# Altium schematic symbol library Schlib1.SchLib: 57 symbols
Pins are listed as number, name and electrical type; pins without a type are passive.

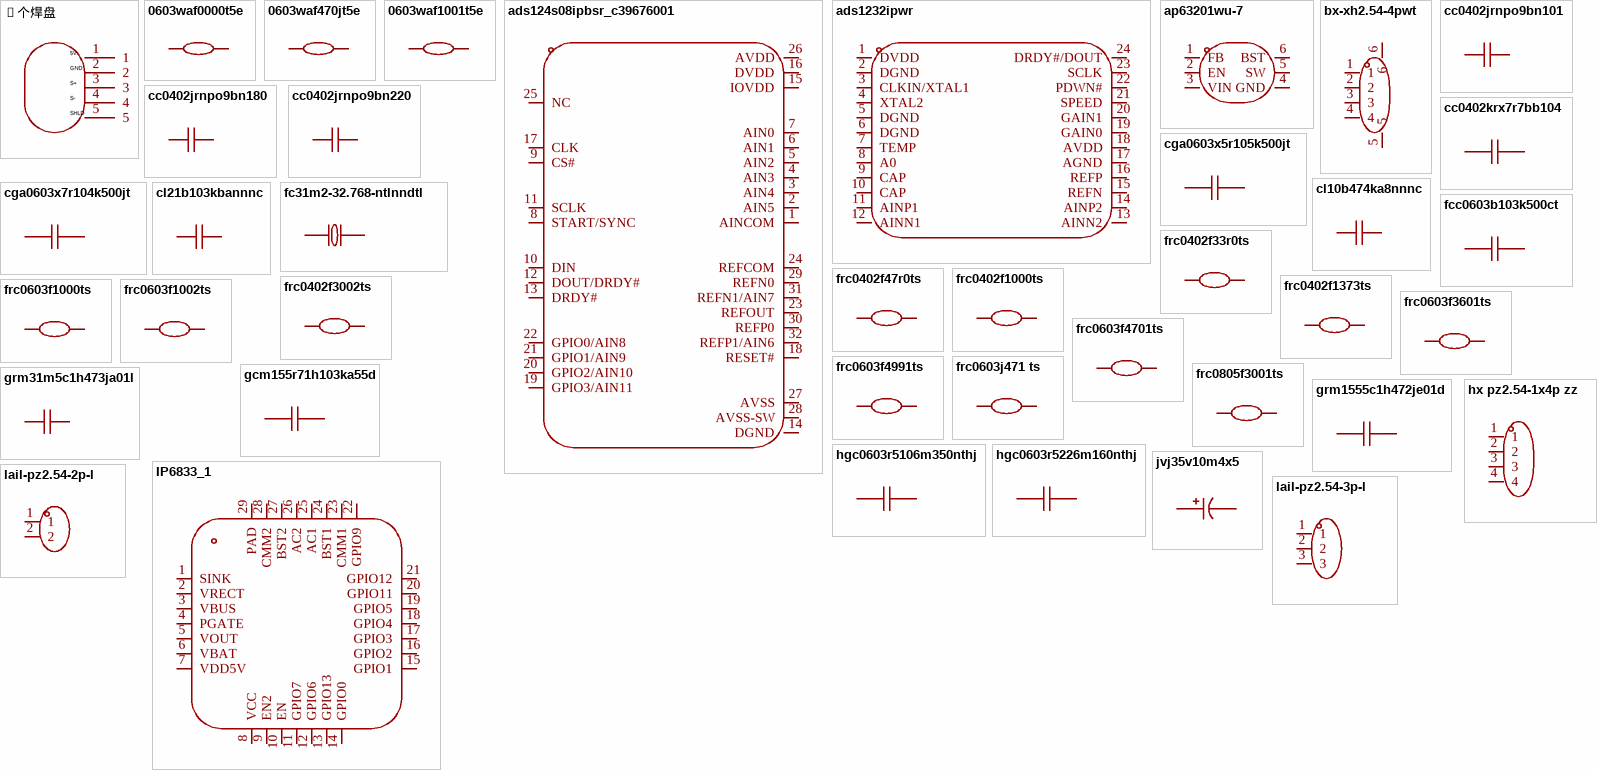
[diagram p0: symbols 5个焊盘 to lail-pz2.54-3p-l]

## 5个焊盘
designator U??  (value not drawn)
Convert to PCB: yes
pins: 1, 2, 3, 4, 5

## 0603waf0000t5e
designator R??  (value not drawn)
电阻类型:厚膜电阻;阻值:0Ω;精度:±1%;功率:100mW;工作电压:75V;温度系数:-;; Manufacturer: UNI-ROYAL(厚声); AddInBom: yes; ModelId: fc143cca1e79419f9cd78b61e9279f08; ModelName: R0603; ModelTransform: 31.8897,63.7794,0,90,0,0,0,0,0; Value: 0Ω; Tolerance: ±1%; Power(Watts): 100mW; Voltage-Supply(Max): 75V
footprint R0603
pins: 1, 2

## 0603waf470jt5e
designator R??  (value not drawn)
电阻类型:厚膜电阻;阻值:47Ω;精度:±1%;功率:100mW;工作电压:75V;温度系数:±100ppm/℃;; Manufacturer: UNI-ROYAL(厚声); AddInBom: yes; ModelId: fc143cca1e79419f9cd78b61e9279f08; ModelName: R0603; ModelTransform: 31.8897,63.7794,0,90,0,0,0,0,0; Value: 47Ω; Tolerance: ±1%; Power(Watts): 100mW; Voltage-Supply(Max): 75V
footprint R0603
pins: 1, 2

## 0603waf1001t5e
designator R??  (value not drawn)
电阻类型:厚膜电阻;阻值:1kΩ;精度:±1%;功率:100mW;工作电压:75V;温度系数:±100ppm/℃;; Manufacturer: UNI-ROYAL(厚声); AddInBom: yes; ModelId: fc143cca1e79419f9cd78b61e9279f08; ModelName: R0603; ModelTransform: 31.8897,63.7794,0,90,0,0,0,0,0; Value: 1kΩ; Tolerance: ±1%; Power(Watts): 100mW; Voltage-Supply(Max): 75V
footprint R0603
pins: 1, 2

## ads124s08ipbsr_c39676001
designator U??  (value not drawn)
分辨率(位):24;采样率:4kHz;工作电压:2.7V~5.25V;接口类型:SPI;; Manufacturer: TI(德州仪器); AddInBom: yes; ModelId: 0723864a05e7424ab80b3c78d6a7d93a; ModelName: TQFP-32_L5.0-W5.0-H1.2-LS7.0-P0.50; ModelTransform: 277.58783,277.58783,0,90,0,0,0.013,0,0; Resolution (Bits): 24; Sampling Rate: 4kHz; number of channels: 12; Interface: SPI; differential input: 是; Clock/Oscillator: 内置; Clock Frequency: 4.096MHz; Programmable Gain: 支持; Quiescent Current (Iq): 280uA
footprint TQFP-32_L5.0-W5.0-P0.50-LS7.0-BL
pins: 1 AINCOM, 2 AIN5, 3 AIN4, 4 AIN3, 5 AIN2, 6 AIN1, 7 AIN0, 8 START/SYNC, 9 CS#, 10 DIN, 11 SCLK, 12 DOUT/DRDY#, 13 DRDY#, 14 DGND, 15 IOVDD, 16 DVDD, 17 CLK, 18 RESET#, 19 GPIO3/AIN11, 20 GPIO2/AIN10, 21 GPIO1/AIN9, 22 GPIO0/AIN8, 23 REFOUT, 24 REFCOM, 25 NC, 26 AVDD, 27 AVSS, 28 AVSS-SW, 29 REFN0, 30 REFP0, 31 REFN1/AIN7, 32 REFP1/AIN6

## ads1232ipwr
designator U??  (value not drawn)
分辨率(位):24;采样率:10Hz;工作电压:2.7V~5.3V;接口类型:SPI;; Manufacturer: TI(德州仪器); AddInBom: yes; ModelId: 57e278220af748a2882c4abba4094eb9; ModelName: TSSOP-24_L7.8-W4.4-H1.0-LS6.4-P0.65; ModelTransform: 252.188,307.086,0,90,0,0,0,0,0; Resolution (Bits): 24; Sampling Rate: 10Hz; number of channels: 2; Interface: SPI; differential input: 是; Clock/Oscillator: 内置；外置; Clock Frequency: 4.9152MHz；200kHz~8MHz; Voltage Reference: 外置; Programmable Gain: 支持; Temperature Sensors: 内置; ADC architecture: Sigma-Delta; Data rate: 80Hz；10Hz; Quiescent Current (Iq): 1.3uA; Full-Scale Range(FSR): 39mV；1.25V；19.5mV；2.5V
footprint TSSOP-24_L7.8-W4.4-P0.65-LS6.4-BL
footprint Model Name (Footprint not found)
pins: 1 DVDD, 2 DGND, 3 CLKIN/XTAL1, 4 XTAL2, 5 DGND, 6 DGND, 7 TEMP, 8 A0, 9 CAP, 10 CAP, 11 AINP1, 12 AINN1, 13 AINN2, 14 AINP2, 15 REFN, 16 REFP, 17 AGND, 18 AVDD, 19 GAIN0, 20 GAIN1, 21 SPEED, 22 PDWN#, 23 SCLK, 24 DRDY#/DOUT

## ap63201wu-7
designator U??  (value not drawn)
功能类型:降压型;工作电压:3.8V~32V;输出电压:-;输出电流:2A;输出类型:可调;; Manufacturer: DIODES(美台); AddInBom: yes; ModelId: 2c4039b5b88644c1bda4b4ba9e971667; ModelName: TSOT-23-6_L2.9-W1.6-H1.1-LS2.8-P0.95; ModelTransform: 110.45568,114.173,0,180,0,0,-0.005,-0.0005,0; Function: 降压型; Output Current: 2A; Frequency - Switching: 500kHz; Synchronous Rectifier: 是; Number of Outputs: 1; Topology: 降压式; Quiescent Current: 22uA; Switch tube (built-in/external): 内置; Output Type: 可调
footprint TSOT-23-6_L2.9-W1.6-P0.95-LS2.8-BR
pins: 1 FB, 2 EN, 3 VIN, 4 GND, 5 SW, 6 BST

## bx-xh2.54-4pwt
designator U??  (value not drawn)
插针结构:1x4P;间距:2.5mm;安装方式:卧贴;参考系列:XH;总PIN数:4P;排数:1;每排PIN数:4;行距:-;额定电流:3A;触头材质:黄铜;触头镀层:锡;工作温度:-25℃~+85℃;; Manufacturer: Bossie(博锡); AddInBom: yes; ModelId: fc4292fdbd0c45d68488b12ac9a84ffb; ModelName: CONN-SMD_4P-P2.50_BX-XH2.54-4PWT; ModelTransform: 590.55,413.385,0,0,0,0,-0.003,-11.339,0; Pins Structure: 1x4P; Pitch: 2.5mm; Reference Series: XH; Number of PINs Per Row: 4; Current Rating: 3A; Voltage Rating: 250V; Supplementary Features: 辅助焊脚; Z-Height of the Board: 6.2mm; X-Length of Bottom Edge on Board (Spacing Line): 15mm; Y-Width of Bottom Edge on Board: 10.5mm
footprint CONN-SMD_4P-P2.50_BX-XH2.54-4PWT
pins: 1, 2, 3, 4, 5, 6

## cc0402jrnpo9bn101
designator C??  (value not drawn)
容值:100pF;精度:±5%;额定电压:50V;温度系数:NP0;; Manufacturer: YAGEO(国巨); AddInBom: yes; ModelId: 36a51122f27c49738f86b3bfa98863e0; ModelName: C0402_L1.0-W0.5-H0.5; ModelTransform: 39.37,19.685,0,0,0,0,0,0,0; Value: 100pF; Tolerance: ±5%; Voltage Rating: 50V; Temperature Coefficient: NP0
footprint C0402
pins: 1, 2

## cc0402jrnpo9bn180
designator C??  (value not drawn)
容值:18pF;精度:±5%;额定电压:50V;温度系数:NP0;; Manufacturer: YAGEO(国巨); AddInBom: yes; ModelId: 36a51122f27c49738f86b3bfa98863e0; ModelName: C0402_L1.0-W0.5-H0.5; ModelTransform: 39.37,19.685,0,0,0,0,0,0,0; Value: 18pF; Tolerance: ±5%; Voltage Rating: 50V; Temperature Coefficient: NP0
footprint C0402
pins: 1, 2

## cc0402jrnpo9bn220
designator C??  (value not drawn)
容值:22pF;精度:±5%;额定电压:50V;温度系数:NP0;; Manufacturer: YAGEO(国巨); AddInBom: yes; ModelId: 36a51122f27c49738f86b3bfa98863e0; ModelName: C0402_L1.0-W0.5-H0.5; ModelTransform: 39.37,19.685,0,0,0,0,0,0,0; Value: 22pF; Tolerance: ±5%; Voltage Rating: 50V; Temperature Coefficient: NP0
footprint C0402
pins: 1, 2

## cc0402krx7r7bb104
designator C??  (value not drawn)
容值:100nF;精度:±10%;额定电压:16V;温度系数:X7R;; Manufacturer: YAGEO(国巨); AddInBom: yes; ModelId: 36a51122f27c49738f86b3bfa98863e0; ModelName: C0402_L1.0-W0.5-H0.5; ModelTransform: 39.37,19.685,0,0,0,0,0,0,0; Value: 100nF; Tolerance: ±10%; Voltage Rating: 16V; Temperature Coefficient: X7R
footprint C0402
pins: 1, 2

## cga0603x5r105k500jt
designator C??  (value not drawn)
容值:1uF;精度:±10%;额定电压:50V;温度系数:X5R;; Manufacturer: HRE(芯声); AddInBom: yes; ModelId: ac125912035d415993ca9572d50418b1; ModelName: C0603_L1.6-W0.8-H0.8; ModelTransform: 62.992,31.496,0,0,0,0,0,0,0; Value: 1uF; Tolerance: ±10%; Voltage Rating: 50V; Temperature Coefficient: X5R
footprint C0603
pins: 1, 2

## cga0603x7r104k500jt
designator C??  (value not drawn)
容值:100nF;精度:±10%;额定电压:50V;温度系数:X7R;; Manufacturer: HRE(芯声); AddInBom: yes; ModelId: ac125912035d415993ca9572d50418b1; ModelName: C0603_L1.6-W0.8-H0.8; ModelTransform: 62.992,31.496,0,0,0,0,0,0,0; Value: 100nF; Tolerance: ±10%; Voltage Rating: 50V; Temperature Coefficient: X7R
footprint C0603
footprint Model Name (Footprint not found)
pins: 1, 2

## cl10b474ka8nnnc
designator C??  (value not drawn)
容值:470nF;精度:±10%;额定电压:25V;温度系数:X7R;; Manufacturer: SAMSUNG(三星); AddInBom: yes; ModelId: ac125912035d415993ca9572d50418b1; ModelName: C0603_L1.6-W0.8-H0.8; ModelTransform: 62.992,31.496,0,0,0,0,0,0,0; Value: 470nF; Tolerance: ±10%; Voltage Rating: 25V; Temperature Coefficient: X7R
footprint C0603
pins: 1, 2

## cl21b103kbannnc
designator C??  (value not drawn)
容值:10nF;精度:±10%;额定电压:50V;温度系数:X7R;; Manufacturer: SAMSUNG(三星); AddInBom: yes; ModelId: 1ba041120af144c991958decab20d241; ModelName: C0805_L2.0-W1.3-H1.3; ModelTransform: 78.74,51.181,0,0,0,0,0,0.0005,0; Value: 10nF; Tolerance: ±10%; Voltage Rating: 50V; Temperature Coefficient: X7R
footprint C0805
pins: 1, 2

## fc31m2-32.768-ntlnndtl
designator U??  (value not drawn)
晶振类型:贴片晶振;频率:32.768kHz;常温频差:±10ppm;负载电容:12.5pF;频率稳定度:±10ppm;; Manufacturer: HCI(杭晶); AddInBom: yes; ModelId: 762d7afc596f4558a373612390f4386d; ModelName: CRYSTAL-SMD_L3.2-W1.5-1; ModelTransform: 125.984,59.055,0,0,0,0,0,0,0; Normal temperature Frequency Tolerance: ±10ppm; Load Capacitance: 12.5pF; Equivalent Series Resistance(ESR): 70kΩ
footprint CRYSTAL-SMD_L3.2-W1.5
pins: 1, 2

## fcc0603b103k500ct
designator C??  (value not drawn)
容值:10nF;精度:±10%;额定电压:50V;温度系数:X7R;; Manufacturer: FOJAN(富捷); AddInBom: yes; ModelId: ac125912035d415993ca9572d50418b1; ModelName: C0603_L1.6-W0.8-H0.8; ModelTransform: 62.992,31.496,0,0,0,0,0,0,0; Value: 10nF; Tolerance: ±10%; Voltage Rating: 50V; Temperature Coefficient: X7R
footprint C0603
pins: 1, 2

## frc0402f33r0ts
designator R??  (value not drawn)
电阻类型:厚膜电阻;阻值:33Ω;精度:±1%;功率:62.5mW;工作电压:50V;温度系数:±100ppm/℃;; Manufacturer: FOJAN(富捷); AddInBom: yes; ModelId: 98c88bc2b9094f218f3a3e30a7012738; ModelName: R0402_L1.0-W0.5-H0.4; ModelTransform: 39.37,19.685,0,0,0,0,0,0,0; Value: 33Ω; Tolerance: ±1%; Power(Watts): 62.5mW; Voltage-Supply(Max): 50V
footprint R0402
pins: 1, 2

## frc0402f47r0ts
designator R??  (value not drawn)
电阻类型:厚膜电阻;阻值:47Ω;精度:±1%;功率:62.5mW;工作电压:50V;温度系数:±100ppm/℃;; Manufacturer: FOJAN(富捷); AddInBom: yes; ModelId: 98c88bc2b9094f218f3a3e30a7012738; ModelName: R0402_L1.0-W0.5-H0.4; ModelTransform: 39.37,19.685,0,0,0,0,0,0,0; Value: 47Ω; Tolerance: ±1%; Power(Watts): 62.5mW; Voltage-Supply(Max): 50V
footprint R0402
pins: 1, 2

## frc0402f1000ts
designator R??  (value not drawn)
电阻类型:厚膜电阻;阻值:100Ω;精度:±1%;功率:62.5mW;工作电压:50V;温度系数:±100ppm/℃;; Manufacturer: FOJAN(富捷); AddInBom: yes; ModelId: 98c88bc2b9094f218f3a3e30a7012738; ModelName: R0402_L1.0-W0.5-H0.4; ModelTransform: 39.37,19.685,0,0,0,0,0,0,0; Value: 100Ω; Tolerance: ±1%; Power(Watts): 62.5mW; Voltage-Supply(Max): 50V
footprint R0402
pins: 1, 2

## frc0402f1373ts
designator R??  (value not drawn)
电阻类型:厚膜电阻;阻值:137kΩ;精度:±1%;功率:62.5mW;工作电压:50V;温度系数:±100ppm/℃;; Manufacturer: FOJAN(富捷); AddInBom: yes; ModelId: 98c88bc2b9094f218f3a3e30a7012738; ModelName: R0402_L1.0-W0.5-H0.4; ModelTransform: 39.37,19.685,0,0,0,0,0,0,0; Value: 137kΩ; Tolerance: ±1%; Power(Watts): 62.5mW; Voltage-Supply(Max): 50V
footprint R0402
pins: 1, 2

## frc0402f3002ts
designator R??  (value not drawn)
电阻类型:厚膜电阻;阻值:30kΩ;精度:±1%;功率:62.5mW;工作电压:50V;温度系数:±100ppm/℃;; Manufacturer: FOJAN(富捷); AddInBom: yes; ModelId: 98c88bc2b9094f218f3a3e30a7012738; ModelName: R0402_L1.0-W0.5-H0.4; ModelTransform: 39.37,19.685,0,0,0,0,0,0,0; Value: 30kΩ; Tolerance: ±1%; Power(Watts): 62.5mW; Voltage-Supply(Max): 50V
footprint R0402
pins: 1, 2

## frc0603f1000ts
designator R??  (value not drawn)
电阻类型:厚膜电阻;阻值:100Ω;精度:±1%;功率:100mW;工作电压:75V;温度系数:±100ppm/℃;; Manufacturer: FOJAN(富捷); AddInBom: yes; ModelId: fc143cca1e79419f9cd78b61e9279f08; ModelName: R0603; ModelTransform: 31.8897,63.7794,0,90,0,0,0,0,0; Value: 100Ω; Tolerance: ±1%; Power(Watts): 100mW; Voltage-Supply(Max): 75V
footprint R0603
pins: 1, 2

## frc0603f1002ts
designator R??  (value not drawn)
电阻类型:厚膜电阻;阻值:10kΩ;精度:±1%;功率:100mW;工作电压:75V;温度系数:±100ppm/℃;; Manufacturer: FOJAN(富捷); AddInBom: yes; ModelId: fc143cca1e79419f9cd78b61e9279f08; ModelName: R0603; ModelTransform: 31.8897,63.7794,0,90,0,0,0,0,0; Value: 10kΩ; Tolerance: ±1%; Power(Watts): 100mW; Voltage-Supply(Max): 75V
footprint R0603
pins: 1, 2

## frc0603f3601ts
designator R??  (value not drawn)
电阻类型:厚膜电阻;阻值:3.6kΩ;精度:±1%;功率:100mW;工作电压:75V;温度系数:±100ppm/℃;; Manufacturer: FOJAN(富捷); AddInBom: yes; ModelId: fc143cca1e79419f9cd78b61e9279f08; ModelName: R0603; ModelTransform: 31.8897,63.7794,0,90,0,0,0,0,0; Value: 3.6kΩ; Tolerance: ±1%; Power(Watts): 100mW; Voltage-Supply(Max): 75V
footprint R0603
pins: 1, 2

## frc0603f4701ts
designator R??  (value not drawn)
电阻类型:厚膜电阻;阻值:4.7kΩ;精度:±1%;功率:100mW;工作电压:75V;温度系数:±100ppm/℃;; Manufacturer: FOJAN(富捷); AddInBom: yes; ModelId: fc143cca1e79419f9cd78b61e9279f08; ModelName: R0603; ModelTransform: 31.8897,63.7794,0,90,0,0,0,0,0; Value: 4.7kΩ; Tolerance: ±1%; Power(Watts): 100mW; Voltage-Supply(Max): 75V
footprint R0603
pins: 1, 2

## frc0603f4991ts
designator R??  (value not drawn)
电阻类型:厚膜电阻;阻值:4.99kΩ;精度:±1%;功率:100mW;工作电压:75V;温度系数:±100ppm/℃;; Manufacturer: FOJAN(富捷); AddInBom: yes; ModelId: fc143cca1e79419f9cd78b61e9279f08; ModelName: R0603; ModelTransform: 31.8897,63.7794,0,90,0,0,0,0,0; Value: 4.99kΩ; Tolerance: ±1%; Power(Watts): 100mW; Voltage-Supply(Max): 75V
footprint R0603
pins: 1, 2

## frc0603j471 ts
designator R??  (value not drawn)
电阻类型:厚膜电阻;阻值:470Ω;精度:±5%;功率:100mW;工作电压:75V;温度系数:±100ppm/℃;; Manufacturer: FOJAN(富捷); AddInBom: yes; ModelId: fc143cca1e79419f9cd78b61e9279f08; ModelName: R0603; ModelTransform: 31.8897,63.7794,0,90,0,0,0,0,0; Value: 470Ω; Tolerance: ±5%; Power(Watts): 100mW; Voltage-Supply(Max): 75V
footprint R0603
pins: 1, 2

## frc0805f3001ts
designator R??  (value not drawn)
电阻类型:厚膜电阻;阻值:3kΩ;精度:±1%;功率:125mW;工作电压:150V;温度系数:±100ppm/℃;; Manufacturer: FOJAN(富捷); AddInBom: yes; ModelId: 37a81e68749a4138bd2dfa6897b24b85; ModelName: R0805_L2.0-W1.3-H0.6; ModelTransform: 78.74,51.181,0,0,0,0,0,-0.0005,0; Value: 3kΩ; Tolerance: ±1%; Power(Watts): 125mW; Voltage-Supply(Max): 150V
footprint R0805
pins: 1, 2

## gcm155r71h103ka55d
designator C??  (value not drawn)
容值:10nF;精度:±10%;额定电压:50V;温度系数:X7R;; Manufacturer: muRata(村田); AddInBom: yes; ModelId: 36a51122f27c49738f86b3bfa98863e0; ModelName: C0402_L1.0-W0.5-H0.5; ModelTransform: 39.37,19.685,0,0,0,0,0,0,0; Value: 10nF; Tolerance: ±10%; Voltage Rating: 50V; Temperature Coefficient: X7R
footprint C0402
pins: 1, 2

## grm31m5c1h473ja01l
designator C??  (value not drawn)
容值:47nF;精度:±5%;额定电压:50V;温度系数:C0G;; Manufacturer: muRata(村田); AddInBom: yes; ModelId: e4be705b945545a48e666415e3682bd8; ModelName: C1206_L3.2-W1.6-H1.3; ModelTransform: 125.984,62.992,0,0,0,0,0,0,0; Value: 47nF; Tolerance: ±5%; Voltage Rating: 50V; Temperature Coefficient: C0G
footprint C1206
pins: 1, 2

## grm1555c1h472je01d
designator C??  (value not drawn)
容值:4.7nF;精度:±5%;额定电压:50V;温度系数:C0G;; Manufacturer: muRata(村田); AddInBom: yes; ModelId: 36a51122f27c49738f86b3bfa98863e0; ModelName: C0402_L1.0-W0.5-H0.5; ModelTransform: 39.37,19.685,0,0,0,0,0,0,0; Value: 4.7nF; Tolerance: ±5%; Voltage Rating: 50V; Temperature Coefficient: C0G
footprint C0402
pins: 1, 2

## hgc0603r5106m350nthj
designator C??  (value not drawn)
容值:10uF;精度:±20%;额定电压:35V;温度系数:X5R;; Manufacturer: Chinocera(华瓷); AddInBom: yes; ModelId: ac125912035d415993ca9572d50418b1; ModelName: C0603_L1.6-W0.8-H0.8; ModelTransform: 62.992,31.496,0,0,0,0,0,0,0; Value: 10uF; Tolerance: ±20%; Voltage Rating: 35V; Temperature Coefficient: X5R
footprint C0603
pins: 1, 2

## hgc0603r5226m160nthj
designator C??  (value not drawn)
容值:22uF;精度:±20%;额定电压:16V;温度系数:X5R;; Manufacturer: Chinocera(华瓷); AddInBom: yes; ModelId: ac125912035d415993ca9572d50418b1; ModelName: C0603_L1.6-W0.8-H0.8; ModelTransform: 62.992,31.496,0,0,0,0,0,0,0; Value: 22uF; Tolerance: ±20%; Voltage Rating: 16V; Temperature Coefficient: X5R
footprint C0603
pins: 1, 2

## hx pz2.54-1x4p zz
designator U??  (value not drawn)
插针结构:1x4P;间距:2.54mm;行距:-;圆针/方针:方针;安装方式:直插;排数:单排;总PIN位数:4P;额定电流:3A;额定电压:1kV;配合针长度:6mm;塑高:2.5mm;端接针长度:3mm;触头材质:黄铜;触头镀层:金;工作温度:-40℃~+105℃;颜色:黑色;; Manufacturer: hanxia(韩下); AddInBom: yes; ModelId: 112f4d05e8d64e99ab9a333894bea4f9; ModelName: HDR-TH_4P-P2.54-M-LI-1X4P; ModelTransform: 399.999,104.7242,0,0,0,0,0,0,-118.11; Pin Structure: 1x4P; Pitch: 2.54mm; Circluar Pins/Square Pins: 方针; Current Rating: 3A; Voltage Rating (Max): 1kV
footprint HDR-TH_4P-P2.54-V-M
pins: 1, 2, 3, 4

## IP6833_1
designator U??  (value not drawn)
pins: 1 SINK, 2 VRECT, 3 VBUS, 4 PGATE, 5 VOUT, 6 VBAT, 7 VDD5V, 8 VCC, 9 EN2, 10 EN, 11 GPIO7, 12 GPIO6, 13 GPIO13, 14 GPIO0, 15 GPIO1, 16 GPIO2, 17 GPIO3, 18 GPIO4, 19 GPIO5, 20 GPIO11, 21 GPIO12, 22 GPIO9, 23 CMM1, 24 BST1, 25 AC1, 26 AC2, 27 BST2, 28 CMM2, 29 PAD

## jvj35v10m4x5
designator C??  (value not drawn)
容值:10uF;精度:±20%;额定电压:35V;纹波电流:14mA@120Hz;; Manufacturer: JIERR(捷而瑞); AddInBom: yes; ModelId: d5abac2407cc4bb7a22453350802a0e2; ModelName: CAP-SMD_L4.3-W4.3-H5.3-LS5.1; ModelTransform: 169.291,181.102,0,90,0,0,0.376,-0.001,0; Value: 10uF; Tolerance: ±20%; Voltage Rating: 35V; Lifetime: 2000hrs@105℃
footprint CAP-SMD_BD4.0-L4.3-W4.3-FD
pins: 1, 2

## lail-pz2.54-2p-l
designator H??  (value not drawn)
插针结构:1x2P;间距:2.54mm;圆针/方针:方针;排数:单排;总PIN位数:2P;额定电流:3A;额定电压:250V;塑高:2.5mm;端接针长度:3mm;触头材质:黄铜;触头镀层:金;工作温度:-25℃~+80℃;颜色:黑色;; Manufacturer: 莱联; AddInBom: yes; Pin Structure: 1x2P; Pitch: 2.54mm; Circluar Pins/Square Pins: 方针; Current Rating: 3A; Voltage Rating (Max): 250V
footprint CONN-TH_LAIL-PZ2.54-2P-L
pins: 1, 2

## lail-pz2.54-3p-l
designator H??  (value not drawn)
插针结构:1x3P;间距:2.54mm;圆针/方针:方针;排数:单排;总PIN位数:3P;额定电流:3A;额定电压:250V;塑高:2.5mm;端接针长度:3mm;触头材质:黄铜;触头镀层:金;工作温度:-25℃~+80℃;颜色:黑色;; Manufacturer: LAILAN(莱联); AddInBom: yes; ModelId: 94a8ffe137b6410295cb18cd3ffd99db; ModelName: HDR-M-2.54_1x3; ModelTransform: 299.9994,100,0,0,0,0,0,0,-118.11; Pin Structure: 1x3P; Pitch: 2.54mm; Circluar Pins/Square Pins: 方针; Current Rating: 3A; Voltage Rating (Max): 250V
footprint HDR-TH_3P-P2.54-V-M-1
pins: 1, 2, 3

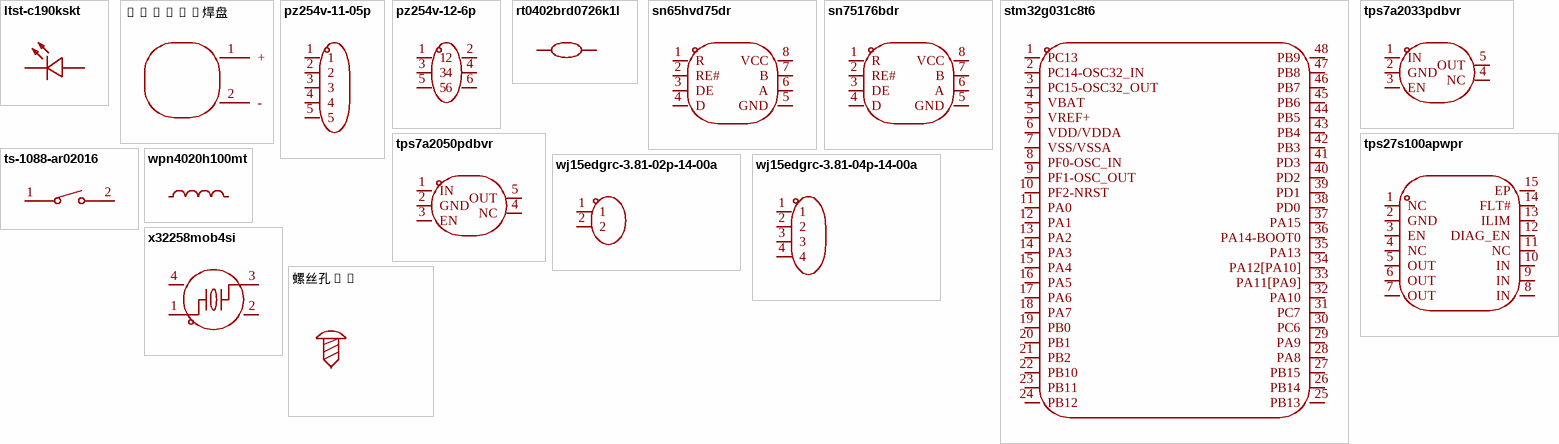
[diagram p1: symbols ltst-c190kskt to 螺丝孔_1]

## ltst-c190kskt
designator LED??  (value not drawn)
灯头类型:-;发光颜色:黄色;正向压降(Vf):2.1V;功率:75mW;正向电流:20mA;波长:584.5nm~597nm;二极管配置:独立二极管;透镜颜色:无色透明透镜;色温:-;发光强度:104mcd;发光角度:130°;载带方式:-;工作温度:-30℃~+85℃;; Manufacturer: LITEON(光宝); AddInBom: yes; ModelId: 1f0d29a91be547639d425604e9b96ebb; ModelName: LED0603-RD; ModelTransform: 63.7794,32.283,0,0,0,0,0,0,0; Illumination Color: 黄色; Voltage - Forward(Vf): 2.1V; Power(Watts): 75mW; Forward Current: 20mA; Peak Wavelength: 588nm; Diode Configuration: 独立二极管; Lens Color: 无色透明透镜; Luminous Intensity: 104mcd; Viewing Angle: 130°
footprint LED0603-RD
pins: 1 -, 2 +

## pt1000焊盘
designator U??  (value not drawn)
AddInBom: yes
footprint PT1000焊盘
pins: 1 +, 2 -

## pz254v-11-05p
designator H??  (value not drawn)
插针结构:1x5P;间距:2.54mm;行距:-;圆针/方针:方针;安装方式:直插;排数:单排;总PIN位数:5P;额定电流:3A;额定电压:250V;配合针长度:6mm;塑高:2.5mm;端接针长度:3mm;触头材质:黄铜;触头镀层:-;工作温度:-40℃~+105℃;颜色:黑色;; Manufacturer: XFCN(兴飞); AddInBom: yes; ModelId: 47d466e4a34f4fc5bc626cf773a24dd5; ModelName: HDR-TH_5P-P2.54-M-LI-1X5P; ModelTransform: 499.999,100,0,0,0,0,0,0,-118.11; Pin Structure: 1x5P; Pitch: 2.54mm; Circluar Pins/Square Pins: 方针; Current Rating: 3A; Voltage Rating (Max): 250V
footprint HDR-TH_5P-P2.54-V-M
pins: 1, 2, 3, 4, 5

## pz254v-12-6p
designator H??  (value not drawn)
插针结构:2x3P;间距:2.54mm;行距:2.54mm;圆针/方针:方针;安装方式:直插;排数:双排;总PIN位数:6P;额定电流:3A;额定电压:-;配合针长度:6mm;塑高:2.5mm;端接针长度:3mm;触头材质:黄铜;触头镀层:金;工作温度:-40℃~+105℃;颜色:黑色;; Manufacturer: XFCN(兴飞); AddInBom: yes; ModelId: e22692306cbd4b5c8488f4142eed6b9c; ModelName: HDR-TH_6P-P2.54-V-M-R2-C3-S2.54; ModelTransform: 300.3931,200,0,0,0,0,0,0,-118.11; Pin Structure: 2x3P; Pitch: 2.54mm; Circluar Pins/Square Pins: 方针; Current Rating: 3A
footprint HDR-TH_6P-P2.54-V-M-R2-C3-S2.54
pins: 1, 2, 3, 4, 5, 6

## rt0402brd0726k1l
designator R??  (value not drawn)
电阻类型:薄膜电阻;阻值:26.1kΩ;精度:±0.1%;功率:62.5mW;工作电压:50V;温度系数:±25ppm/℃;; Manufacturer: YAGEO(国巨); AddInBom: yes; ModelId: 98c88bc2b9094f218f3a3e30a7012738; ModelName: R0402_L1.0-W0.5-H0.4; ModelTransform: 39.37,19.685,0,0,0,0,0,0,0; Value: 26.1kΩ; Tolerance: ±0.1%; Power(Watts): 62.5mW; Voltage-Supply(Max): 50V
footprint R0402
pins: 1, 2

## sn65hvd75dr
designator U??  (value not drawn)
类型:收发器;数据速率:20Mbps;; Manufacturer: TI(德州仪器); AddInBom: yes; ModelId: e81d2f7d937b4a6ab1dca543ff5d56a4; ModelName: SOIC-8_L4.9-W3.9-H1.7-LS6.0-P1.27; ModelTransform: 192.913,236.22,0,0,0,0,0,0,0; Number of Drivers: 1; Voltage - Supply: 3V~3.6V; Data Rate: 20Mbps; Number of Nodes: 213; ESD Protect: ±15kV; Quiescent Supply Current: 950uA; Communication Mode: 半双工
footprint SOIC-8_L4.9-W3.9-P1.27-LS6.0-BL
pins: 1 R, 2 RE#, 3 DE, 4 D, 5 GND, 6 A, 7 B, 8 VCC

## sn75176bdr
designator U??  (value not drawn)
类型:收发器;数据速率:-;; Manufacturer: TI(德州仪器); AddInBom: yes; ModelId: 7abc64c95a1a4a04a4ef38f9097c870b; ModelName: SOIC-8_L5.0-W4.0-P1.27-LS6.0-BL; ModelTransform: 192.913,236.22,0,0,0,0,0,0,0; Number of Drivers: 1; Voltage - Supply: 4.75V~5.25V
footprint SOIC-8_L5.0-W4.0-P1.27-LS6.0-BL
pins: 1 R, 2 RE#, 3 DE, 4 D, 5 GND, 6 A, 7 B, 8 VCC

## stm32g031c8t6
designator U??  (value not drawn)
CPU内核:ARM Cortex-M0+;CPU最大主频:64MHz;CPU位数:32 Bit;; Manufacturer: ST(意法半导体); AddInBom: yes; ModelId: 093be70396ff421eb2cdb946d5311efc; ModelName: LQFP-48_L7.0-W7.0-H1.4-LS9.0-P0.50; ModelTransform: 354.331,354.331,0,0,0,0,0,0,0; CPU Maximum Speed: 64MHz; Core Size: 32 Bit; Program Storage Size: 64KB; Program Memory Type: FLASH; RAM Size: 8KB; Number of I/O: 44; ADC (Bit): 12bit; Oscillator Type: 内置+外置; Voltage - Supply: 1.7V~3.6V
footprint LQFP-48_L7.0-W7.0-P0.50-LS9.0-BL
pins: 1 PC13, 2 PC14-OSC32_IN, 3 PC15-OSC32_OUT, 4 VBAT, 5 VREF+, 6 VDD/VDDA, 7 VSS/VSSA, 8 PF0-OSC_IN, 9 PF1-OSC_OUT, 10 PF2-NRST, 11 PA0, 12 PA1, 13 PA2, 14 PA3, 15 PA4, 16 PA5, 17 PA6, 18 PA7, 19 PB0, 20 PB1, 21 PB2, 22 PB10, 23 PB11, 24 PB12, 25 PB13, 26 PB14, 27 PB15, 28 PA8, 29 PA9, 30 PC6, 31 PC7, 32 PA10, 33 PA11[PA9], 34 PA12[PA10], 35 PA13, 36 PA14-BOOT0, 37 PA15, 38 PD0, 39 PD1, 40 PD2, 41 PD3, 42 PB3, 43 PB4, 44 PB5, 45 PB6, 46 PB7, 47 PB8, 48 PB9

## tps7a2033pdbvr
designator U??  (value not drawn)
输出类型:固定;最大输入电压:6V;输出电压:3.3V;输出电流:300mA;输出极性:正极;; Manufacturer: TI(德州仪器); AddInBom: yes; ModelId: 7ba65df16e7b4570af156e925f9c37fe; ModelName: SOT-23-5_L2.9-W1.6-P0.95-LS2.8-BR; ModelTransform: 114.173,114.173,0,90,0,0,0,0,0; Output Type: 固定; Maximum Input Voltage: 6V; Output Voltage: 3.3V; Output Current: 300mA; Dropout Voltage: 140mV@(300mA); standby current: 15uA; Output Polarity: 正极; Number of Outputs: 1
footprint SOT-23-5_L2.9-W1.6-P0.95-LS2.8-BR
pins: 1 IN, 2 GND, 3 EN, 4 NC, 5 OUT

## tps7a2050pdbvr
designator U??  (value not drawn)
输出极性:正极;工作电压:6V;输出电压:5V;输出电流:300mA;电源纹波抑制比(PSRR):65dB@(100Hz);输出类型:固定;; Manufacturer: TI(德州仪器); AddInBom: yes; ModelId: 7ba65df16e7b4570af156e925f9c37fe; ModelName: SOT-23-5_L2.9-W1.6-P0.95-LS2.8-BR; ModelTransform: 114.173,114.173,0,90,0,0,0,0,0; Output Configuration: 正极; Voltage - Supply: 6V; Output Voltage: 5V; Output Current: 300mA; Voltage Dropout: 140mV@(300mA); standby current: 6.5uA; Noise: 10uVrms; Output Type: 固定; Number of Outputs: 1
footprint SOT-23-5_L2.9-W1.6-P0.95-LS2.8-BR
pins: 1 IN, 2 GND, 3 EN, 4 NC, 5 OUT

## tps27s100apwpr
designator U??  (value not drawn)
类型:高侧开关;通道数:1;输入控制逻辑:高电平有效;工作电压:3.5V~40V;最大连续电流:4A;导通电阻:80mΩ;; Manufacturer: TI(德州仪器); AddInBom: yes; ModelId: 02f1f60386074b2ca8e111040ac061f2; ModelName: TSSOP-14_L5.0-W4.4-H1.0-LS6.4-P0.65; ModelTransform: 236.714,196.85,0,90,0,0,0,0.0005,0; Number of Channels: 1; Control Input Logic: 高电平有效; Maximum Continuous Current: 4A; RDS(on): 80mΩ
footprint TSSOP-14_L5.0-W4.4-P0.65-LS6.4-BL-EP
pins: 1 NC, 2 GND, 3 EN, 4 NC, 5 OUT, 6 OUT, 7 OUT, 8 IN, 9 IN, 10 IN, 11 NC, 12 DIAG_EN, 13 ILIM, 14 FLT#, 15 EP

## ts-1088-ar02016
designator SW??  (value not drawn)
电路结构:单刀单掷;按钮形状:圆形按钮;作用力:1.6N;安装方式:立贴;开关长度:3.9mm;开关宽度:3mm;开关高度:2mm;带支架:不带支架;触点电流:50mA;额定电压:12V;带灯:-;工作寿命:10万次;; Manufacturer: XUNPU(讯普); AddInBom: yes; ModelId: b26698b69f274ffabef8a26c7d0e5dd1; ModelName: SW-SMD_L3.9-W2.9-H2.0-LS4.8; ModelTransform: 188.976,114.174,0,0,0,0,0,0,0; Circuit: 单刀单掷; Actuator Style: 圆形按钮; Operating Force: 1.6N; Switch Height: 2mm; with Bracket: 不带支架; Contact Current: 50mA; Voltage Rating: 12V; Actuator/Cap Color: 黑色; Life: 10万次
footprint SW-SMD_L3.9-W3.0-P4.45
pins: 1, 2

## wj15edgrc-3.81-02p-14-00a
designator P??  (value not drawn)
连接器类型:板端/插座-闭口;固定方式:无固定装置;结构:1x2P;间距:3.81mm;颜色:绿色;安装方式:弯插;排数:1;每排PIN数:2;额定电流:8A;额定电压:300V;线规 - AWG:-;线规 - 平方毫米:-;工作温度:-40℃~+105℃;; Manufacturer: KANGNEX(康奈克斯电气); Symbol: WJ15EDGRC-3.81-2P; AddInBom: yes; ModelId: 816ec8aca6fe4785be70cb4c5121258d; ModelName: CONN-TH_2P_L8.5-W9.2-H7.0-P3.81; ModelTransform: 334.645,360.2355,0,0,0,0,0,-118.11,-137.795; Number of Positions or Pins: 1x2P; Pitch: 3.81mm; Number of PINs Per Row: 2; Current Rating: 8A; Voltage Rating (Max): 300V
footprint CONN-TH_2P-P3.81_WJ15EDGRC-3.81-2P
pins: 1, 2

## wj15edgrc-3.81-04p-14-00a
designator CN??  (value not drawn)
连接器类型:板端/插座-闭口;固定方式:无固定装置;结构:1x4P;间距:3.81mm;颜色:绿色;安装方式:弯插;排数:1;每排PIN数:4;额定电流:8A;额定电压:300V;线规 - AWG:-;线规 - 平方毫米:-;工作温度:-40℃~+105℃;; Manufacturer: KANGNEX(康奈克斯电气); Symbol: WJ15EDGRC-3.81-4P; AddInBom: yes; ModelId: 4512f1cc0fee4248839d43b222858c36; ModelName: CONN-TH_4P_L16.1-W9.2-H7.0-P3.81; ModelTransform: 634.6483,360.2355,0,0,0,0,0,-117.126,-137.795; Number of Positions or Pins: 1x4P; Pitch: 3.81mm; Number of PINs Per Row: 4; Current Rating: 8A; Voltage Rating (Max): 300V
footprint CONN-TH_WJ15EDGRC-3.81-4P
pins: 1, 2, 3, 4

## wpn4020h100mt
designator L??  (value not drawn)
电感值:10uH;精度:±20%;额定电流:2A;饱和电流(Isat):3.5A;类型:-;; Manufacturer: Sunlord(顺络); AddInBom: yes; ModelId: 45bc3737ecfd4f3bb122605ee525b018; ModelName: IND-SMD_L4.0-W4.0-H1.9; ModelTransform: 157.48,157.484,0,0,0,0,0,0,0; Value: 10uH; Tolerance: ±20%; Current Rating: 2A; Current - Saturation(Isat): 3.5A; DC Resistance(DCR): 216mΩ
footprint IND-SMD_L4.0-W4.0
pins: 1, 2

## x32258mob4si
designator X??  (value not drawn)
晶振类型:贴片晶振;频率:8MHz;常温频差:±10ppm;负载电容:12pF;频率稳定度:±20ppm;; Manufacturer: YXC(扬兴晶振); AddInBom: yes; ModelId: ff2dfd5650294453a14147960efe1838; ModelName: CRYSTAL-SMD_4P-L3.2-W2.5-BL; ModelTransform: 125.984,98.425,0,0,0,0,0,0,0; Value: 8MHz; Normal temperature Frequency Tolerance: ±10ppm; Load Capacitance: 12pF; Frequency Stability: ±20ppm; Equivalent Series Resistance(ESR): 180Ω
footprint CRYSTAL-SMD_4P-L3.2-W2.5-BL
pins: 1, 2 GND, 3, 4 GND

## 螺丝孔_1
designator *?  (value not drawn)
footprint M3螺丝
pins: 1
